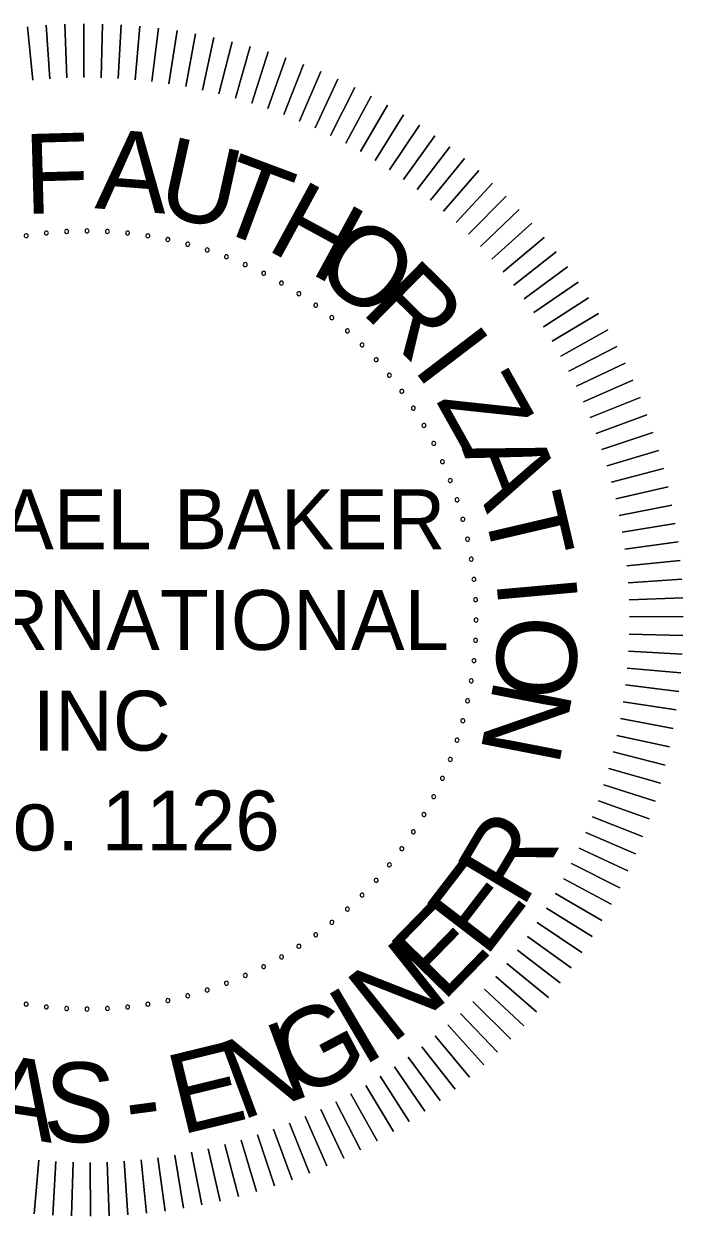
# Model space of a CAD drawing. Extents: x -4306 to 3843, y 131 to 8053.
# Drawn here: x 2834.9 to 2972.5, y 322.6 to 571.4 of the extents above; entities that cross this region are included whole.
import ezdxf

# ---------------------------------------------------------------- set-up
doc = ezdxf.new("R2010")
doc.units = 0
doc.layers.add('G-ANNO-TEXT', color=7, linetype='Continuous')

msp = doc.modelspace()

# ---------------------------------------------------------------- linework, layer by layer
at = {"layer": 'G-ANNO-TEXT'}
for points in [[(2836.77, 559.65), (2835.65, 570.82)], [(2835.65, 570.82), (2836.77, 559.65)], [(2840.32, 559.95), (2839.55, 571.14)], [(2839.55, 571.14), (2840.32, 559.95)], [(2843.87, 560.13), (2843.45, 571.35)], [(2843.45, 571.35), (2843.87, 560.13)], [(2847.42, 560.21), (2847.36, 571.43)], [(2847.36, 571.43), (2847.42, 560.21)], [(2850.98, 560.17), (2851.27, 571.39)], [(2851.27, 571.39), (2850.98, 560.17)], [(2854.53, 560.03), (2855.18, 571.23)], [(2855.18, 571.23), (2854.53, 560.03)], [(2858.08, 559.77), (2859.08, 570.95)], [(2859.08, 570.95), (2858.08, 559.77)], [(2861.62, 559.4), (2862.96, 570.54)], [(2862.96, 570.54), (2861.62, 559.4)], [(2865.14, 558.92), (2866.84, 570.01)], [(2866.84, 570.01), (2865.14, 558.92)], [(2868.65, 558.32), (2870.69, 569.36)], [(2870.69, 569.36), (2868.65, 558.32)], [(2872.14, 557.62), (2874.52, 568.59)], [(2874.52, 568.59), (2872.14, 557.62)], [(2875.6, 556.81), (2878.33, 567.7)], [(2878.33, 567.7), (2875.6, 556.81)], [(2879.04, 555.89), (2882.11, 566.69)], [(2882.11, 566.69), (2879.04, 555.89)], [(2882.44, 554.86), (2885.85, 565.56)], [(2885.85, 565.56), (2882.44, 554.86)], [(2885.81, 553.73), (2889.56, 564.31)], [(2889.56, 564.31), (2885.81, 553.73)], [(2889.15, 552.49), (2893.22, 562.95)], [(2893.22, 562.95), (2889.15, 552.49)], [(2892.44, 551.15), (2896.84, 561.47)], [(2896.84, 561.47), (2892.44, 551.15)], [(2895.69, 549.7), (2900.41, 559.88)], [(2900.41, 559.88), (2895.69, 549.7)], [(2898.89, 548.16), (2903.93, 558.18)], [(2903.93, 558.18), (2898.89, 548.16)], [(2902.05, 546.51), (2907.4, 556.37)], [(2907.4, 556.37), (2902.05, 546.51)], [(2905.14, 544.77), (2910.8, 554.46)], [(2910.8, 554.46), (2905.14, 544.77)], [(2908.19, 542.92), (2914.15, 552.43)], [(2914.15, 552.43), (2908.19, 542.92)], [(2911.17, 540.99), (2917.43, 550.3)], [(2917.43, 550.3), (2911.17, 540.99)], [(2914.09, 538.96), (2920.64, 548.07)], [(2920.64, 548.07), (2914.09, 538.96)], [(2916.95, 536.84), (2923.78, 545.74)], [(2923.78, 545.74), (2916.95, 536.84)], [(2919.74, 534.63), (2926.84, 543.32)], [(2926.84, 543.32), (2919.74, 534.63)], [(2922.45, 532.34), (2929.83, 540.8)], [(2929.83, 540.8), (2922.45, 532.34)], [(2932.73, 538.18), (2925.1, 529.96)], [(2925.1, 529.96), (2932.73, 538.18)], [(2935.56, 535.48), (2927.67, 527.5)], [(2927.67, 527.5), (2935.56, 535.48)], [(2938.29, 532.68), (2930.16, 524.96)], [(2930.16, 524.96), (2938.29, 532.68)], [(2940.94, 529.81), (2932.56, 522.34)], [(2932.56, 522.34), (2940.94, 529.81)], [(2943.5, 526.85), (2934.89, 519.65)], [(2934.89, 519.65), (2943.5, 526.85)], [(2945.96, 523.81), (2937.13, 516.88)], [(2937.13, 516.88), (2945.96, 523.81)], [(2948.32, 520.7), (2939.28, 514.05)], [(2939.28, 514.05), (2948.32, 520.7)], [(2950.59, 517.51), (2941.34, 511.15)], [(2941.34, 511.15), (2950.59, 517.51)], [(2952.75, 514.26), (2943.31, 508.19)], [(2943.31, 508.19), (2952.75, 514.26)], [(2954.81, 510.94), (2945.18, 505.17)], [(2945.18, 505.17), (2954.81, 510.94)], [(2956.77, 507.55), (2946.96, 502.09)], [(2946.96, 502.09), (2956.77, 507.55)], [(2958.62, 504.11), (2948.65, 498.96)], [(2948.65, 498.96), (2958.62, 504.11)], [(2960.36, 500.6), (2950.23, 495.77)], [(2950.23, 495.77), (2960.36, 500.6)], [(2961.98, 497.05), (2951.71, 492.54)], [(2951.71, 492.54), (2961.98, 497.05)], [(2963.5, 493.45), (2953.09, 489.26)], [(2953.09, 489.26), (2963.5, 493.45)], [(2964.9, 489.8), (2954.37, 485.94)], [(2954.37, 485.94), (2964.9, 489.8)], [(2966.19, 486.11), (2955.54, 482.58)], [(2955.54, 482.58), (2966.19, 486.11)], [(2967.36, 482.38), (2956.6, 479.19)], [(2956.6, 479.19), (2967.36, 482.38)], [(2968.41, 478.61), (2957.56, 475.76)], [(2957.56, 475.76), (2968.41, 478.61)], [(2969.35, 474.82), (2958.41, 472.31)], [(2958.41, 472.31), (2969.35, 474.82)], [(2970.16, 470.99), (2959.15, 468.83)], [(2959.15, 468.83), (2970.16, 470.99)], [(2970.85, 467.15), (2959.78, 465.33)], [(2959.78, 465.33), (2970.85, 467.15)], [(2971.43, 463.28), (2960.3, 461.81)], [(2960.3, 461.81), (2971.43, 463.28)], [(2971.88, 459.39), (2960.71, 458.28)], [(2960.71, 458.28), (2971.88, 459.39)], [(2972.21, 455.5), (2961.01, 454.73)], [(2961.01, 454.73), (2972.21, 455.5)], [(2972.41, 451.6), (2961.2, 451.18)], [(2961.2, 451.18), (2972.41, 451.6)], [(2972.49, 447.69), (2961.27, 447.62)], [(2961.27, 447.62), (2972.49, 447.69)], [(2972.46, 443.78), (2961.24, 444.07)], [(2961.24, 444.07), (2972.46, 443.78)], [(2972.29, 439.87), (2961.09, 440.51)], [(2961.09, 440.51), (2972.29, 439.87)], [(2972.01, 435.97), (2960.83, 436.97)], [(2960.83, 436.97), (2972.01, 435.97)], [(2971.6, 432.09), (2960.46, 433.43)], [(2960.46, 433.43), (2971.6, 432.09)], [(2971.07, 428.21), (2959.98, 429.91)], [(2959.98, 429.91), (2971.07, 428.21)], [(2970.42, 424.36), (2959.39, 426.4)], [(2959.39, 426.4), (2970.42, 424.36)], [(2969.65, 420.52), (2958.68, 422.91)], [(2958.68, 422.91), (2969.65, 420.52)], [(2968.76, 416.72), (2957.87, 419.45)], [(2957.87, 419.45), (2968.76, 416.72)], [(2967.75, 412.94), (2956.95, 416.01)], [(2956.95, 416.01), (2967.75, 412.94)], [(2966.62, 409.2), (2955.93, 412.61)], [(2955.93, 412.61), (2966.62, 409.2)], [(2965.37, 405.49), (2954.79, 409.24)], [(2954.79, 409.24), (2965.37, 405.49)], [(2964.01, 401.83), (2953.55, 405.9)], [(2953.55, 405.9), (2964.01, 401.83)], [(2962.54, 398.21), (2952.21, 402.61)], [(2952.21, 402.61), (2962.54, 398.21)], [(2960.95, 394.64), (2950.77, 399.36)], [(2950.77, 399.36), (2960.95, 394.64)], [(2959.25, 391.12), (2949.22, 396.16)], [(2949.22, 396.16), (2959.25, 391.12)], [(2957.44, 387.65), (2947.57, 393)], [(2947.57, 393), (2957.44, 387.65)], [(2955.52, 384.25), (2945.83, 389.9)], [(2945.83, 389.9), (2955.52, 384.25)], [(2953.49, 380.9), (2943.99, 386.86)], [(2943.99, 386.86), (2953.49, 380.9)], [(2951.37, 377.62), (2942.05, 383.88)], [(2942.05, 383.88), (2951.37, 377.62)], [(2949.14, 374.41), (2940.02, 380.96)], [(2940.02, 380.96), (2949.14, 374.41)], [(2946.81, 371.27), (2937.9, 378.1)], [(2937.9, 378.1), (2946.81, 371.27)], [(2944.38, 368.21), (2935.69, 375.31)], [(2935.69, 375.31), (2944.38, 368.21)], [(2941.86, 365.22), (2933.4, 372.6)], [(2933.4, 372.6), (2941.86, 365.22)], [(2939.24, 362.31), (2931.02, 369.95)], [(2931.02, 369.95), (2939.24, 362.31)], [(2936.54, 359.49), (2928.56, 367.38)], [(2928.56, 367.38), (2936.54, 359.49)], [(2933.75, 356.76), (2926.02, 364.89)], [(2926.02, 364.89), (2933.75, 356.76)], [(2930.87, 354.11), (2923.4, 362.49)], [(2923.4, 362.49), (2930.87, 354.11)], [(2927.91, 351.55), (2920.71, 360.16)], [(2920.71, 360.16), (2927.91, 351.55)], [(2924.87, 349.09), (2917.95, 357.92)], [(2917.95, 357.92), (2924.87, 349.09)], [(2918.57, 344.46), (2912.21, 353.71)], [(2912.21, 353.71), (2918.57, 344.46)], [(2921.76, 346.73), (2915.11, 355.77)], [(2915.11, 355.77), (2921.76, 346.73)], [(2915.32, 342.3), (2909.25, 351.74)], [(2909.25, 351.74), (2915.32, 342.3)], [(2912, 340.24), (2906.23, 349.86)], [(2906.23, 349.86), (2912, 340.24)], [(2905.17, 336.43), (2900.02, 346.4)], [(2900.02, 346.4), (2905.17, 336.43)], [(2908.61, 338.28), (2903.15, 348.08)], [(2903.15, 348.08), (2908.61, 338.28)], [(2901.67, 334.69), (2896.83, 344.82)], [(2896.83, 344.82), (2901.67, 334.69)], [(2894.51, 331.55), (2890.32, 341.96)], [(2890.32, 341.96), (2894.51, 331.55)], [(2898.11, 333.06), (2893.6, 343.34)], [(2893.6, 343.34), (2898.11, 333.06)], [(2887.17, 328.86), (2883.64, 339.51)], [(2883.64, 339.51), (2887.17, 328.86)], [(2890.86, 330.15), (2887, 340.68)], [(2887, 340.68), (2890.86, 330.15)], [(2875.88, 325.7), (2873.37, 336.64)], [(2873.37, 336.64), (2875.88, 325.7)], [(2879.67, 326.64), (2876.82, 337.49)], [(2876.82, 337.49), (2879.67, 326.64)], [(2883.44, 327.69), (2880.25, 338.45)], [(2880.25, 338.45), (2883.44, 327.69)], [(2837.04, 323.04), (2838.03, 334.22)], [(2838.03, 334.22), (2837.04, 323.04)], [(2840.93, 322.76), (2841.58, 333.96)], [(2841.58, 333.96), (2840.93, 322.76)], [(2844.84, 322.59), (2845.13, 333.81)], [(2845.13, 333.81), (2844.84, 322.59)], [(2848.75, 322.55), (2848.69, 333.78)], [(2848.69, 333.78), (2848.75, 322.55)], [(2852.66, 322.64), (2852.24, 333.85)], [(2852.24, 333.85), (2852.66, 322.64)], [(2856.56, 322.84), (2855.79, 334.04)], [(2855.79, 334.04), (2856.56, 322.84)], [(2860.46, 323.17), (2859.34, 334.34)], [(2859.34, 334.34), (2860.46, 323.17)], [(2864.34, 323.62), (2862.87, 334.75)], [(2862.87, 334.75), (2864.34, 323.62)], [(2868.21, 324.19), (2866.39, 335.27)], [(2866.39, 335.27), (2868.21, 324.19)], [(2872.05, 324.89), (2869.89, 335.9)], [(2869.89, 335.9), (2872.05, 324.89)]]:
    msp.add_lwpolyline(points, dxfattribs=at)
for centre, start, end in [((2835.35, 527.21), 9, 189), ((2839.57, 527.76), 6, 186), ((2839.57, 527.76), 186, 6), ((2843.8, 528.1), 3, 183), ((2843.8, 528.1), 183, 3), ((2848.06, 528.21), 0, 180), ((2848.06, 528.21), 180, 0), ((2852.31, 528.1), 357, 177), ((2852.31, 528.1), 177, 357), ((2856.54, 527.76), 354, 174), ((2856.54, 527.76), 174, 354), ((2860.76, 527.21), 351, 171), ((2835.35, 527.21), 189, 9), ((2860.76, 527.21), 171, 351), ((2864.94, 526.43), 168, 348), ((2864.94, 526.43), 348, 168), ((2869.08, 525.44), 165, 345), ((2869.08, 525.44), 345, 165), ((2873.15, 524.23), 162, 342), ((2873.15, 524.23), 342, 162), ((2877.16, 522.81), 159, 339), ((2877.16, 522.81), 339, 159), ((2881.09, 521.19), 156, 336), ((2881.09, 521.19), 336, 156), ((2884.93, 519.36), 153, 333), ((2884.93, 519.36), 333, 153), ((2888.66, 517.33), 330, 150), ((2888.66, 517.33), 150, 330), ((2892.29, 515.11), 147, 327), ((2892.29, 515.11), 327, 147), ((2895.79, 512.7), 144, 324), ((2895.79, 512.7), 324, 144), ((2899.17, 510.11), 141, 321), ((2899.17, 510.11), 321, 141), ((2902.4, 507.35), 318, 138), ((2902.4, 507.35), 138, 318), ((2905.48, 504.42), 135, 315), ((2905.48, 504.42), 315, 135), ((2908.41, 501.34), 132, 312), ((2908.41, 501.34), 312, 132), ((2911.17, 498.1), 129, 309), ((2911.17, 498.1), 309, 129), ((2913.76, 494.73), 126, 306), ((2913.76, 494.73), 306, 126), ((2916.17, 491.23), 123, 303), ((2916.17, 491.23), 303, 123), ((2918.39, 487.6), 120, 300), ((2918.39, 487.6), 300, 120), ((2920.42, 483.86), 117, 297), ((2920.42, 483.86), 297, 117), ((2922.25, 480.03), 114, 294), ((2922.25, 480.03), 294, 114), ((2923.88, 476.1), 111, 291), ((2923.88, 476.1), 291, 111), ((2925.3, 472.09), 108, 288), ((2925.3, 472.09), 288, 108), ((2926.5, 468.01), 105, 285), ((2926.5, 468.01), 285, 105), ((2927.5, 463.88), 102, 282), ((2927.5, 463.88), 282, 102), ((2928.27, 459.7), 99, 279), ((2928.27, 459.7), 279, 99), ((2928.83, 455.48), 96, 276), ((2928.83, 455.48), 276, 96), ((2929.16, 451.24), 93, 273), ((2929.16, 451.24), 273, 93), ((2929.27, 446.99), 90, 270), ((2929.27, 446.99), 270, 90), ((2929.16, 442.74), 87, 267), ((2929.16, 442.74), 267, 87), ((2928.83, 438.5), 84, 264), ((2928.83, 438.5), 264, 84), ((2928.27, 434.29), 81, 261), ((2928.27, 434.29), 261, 81), ((2927.5, 430.11), 78, 258), ((2927.5, 430.11), 258, 78), ((2926.5, 425.97), 75, 255), ((2926.5, 425.97), 255, 75), ((2925.3, 421.9), 72, 252), ((2925.3, 421.9), 252, 72), ((2923.88, 417.89), 69, 249), ((2923.88, 417.89), 249, 69), ((2922.25, 413.96), 66, 246), ((2922.25, 413.96), 246, 66), ((2920.42, 410.12), 63, 243), ((2920.42, 410.12), 243, 63), ((2918.39, 406.39), 60, 240), ((2918.39, 406.39), 240, 60), ((2916.17, 402.76), 57, 237), ((2916.17, 402.76), 237, 57), ((2913.76, 399.26), 54, 234), ((2913.76, 399.26), 234, 54), ((2911.17, 395.88), 51, 231), ((2911.17, 395.88), 231, 51), ((2908.41, 392.65), 48, 228), ((2908.41, 392.65), 228, 48), ((2905.48, 389.57), 45, 225), ((2905.48, 389.57), 225, 45), ((2902.4, 386.64), 42, 222), ((2902.4, 386.64), 222, 42), ((2899.17, 383.88), 39, 219), ((2899.17, 383.88), 219, 39), ((2895.79, 381.29), 36, 216), ((2895.79, 381.29), 216, 36), ((2892.29, 378.88), 33, 213), ((2892.29, 378.88), 213, 33), ((2888.66, 376.66), 30, 210), ((2888.66, 376.66), 210, 30), ((2884.93, 374.63), 27, 207), ((2884.93, 374.63), 207, 27), ((2877.16, 371.17), 21, 201), ((2877.16, 371.17), 201, 21), ((2881.09, 372.8), 24, 204), ((2881.09, 372.8), 204, 24), ((2869.08, 368.55), 15, 195), ((2869.08, 368.55), 195, 15), ((2873.15, 369.75), 18, 198), ((2873.15, 369.75), 198, 18), ((2835.35, 366.78), 171, 351), ((2835.35, 366.78), 351, 171), ((2839.57, 366.22), 354, 174), ((2839.57, 366.22), 174, 354), ((2843.8, 365.89), 357, 177), ((2843.8, 365.89), 177, 357), ((2848.06, 365.78), 0, 180), ((2852.31, 365.89), 3, 183), ((2852.31, 365.89), 183, 3), ((2856.54, 366.22), 6, 186), ((2856.54, 366.22), 186, 6), ((2860.76, 366.78), 9, 189), ((2860.76, 366.78), 189, 9), ((2864.94, 367.55), 12, 192), ((2864.94, 367.55), 192, 12), ((2848.06, 365.78), 180, 0)]:
    msp.add_arc(centre, 0.417, start, end, dxfattribs=at)

# ---------------------------------------------------------------- texts
for s, rotation, p in [('F', 1.5867, (2835.12, 531.73)), ('A', 355.5955, (2849.57, 532.95)), ('U', 347.5481, (2862.18, 531.76)), ('T', 339.5007, (2873.82, 528.98)), ('H', 331.4533, (2885.12, 524.52)), ('O', 323.4059, (2894.69, 519.25)), ('R', 315.3585, (2905.02, 511.35)), ('I', 307.3112, (2915.86, 499.61)), ('Z', 299.2638, (2920.75, 492.82)), ('A', 291.2164, (2926.22, 482.8)), ('T', 283.169, (2930.57, 471)), ('I', 275.1216, (2933.46, 455.4)), ('O', 267.0743, (2934.05, 448.24)), ('N', 259.0269, (2933.17, 435.14)), ('R', 59.2262, (2938.92, 386.55)), ('E', 52.4765, (2931.19, 376.29)), ('E', 45.7268, (2922.3, 367.01)), ('N', 38.4196, (2911.53, 358.22)), ('I', 30.5495, (2905.47, 353.63)), ('G', 27.7404, (2892.3, 346.63)), ('N', 20.4332, (2880.16, 342.43)), ('E', 13.6835, (2867.6, 339.49)), ('A', 351.1991, (2826, 340.11)), ('S', 357.9489, (2838.72, 338.26)), ('-', 7.5077, (2856.91, 338.22))]:
    msp.add_text(s, height=16.67, rotation=rotation, dxfattribs=at).set_placement(p)
for s, height, p in [('MICHAEL BAKER', 12.5016, (2787.23, 461.77)), (' INTERNATIONAL', 12.5016, (2785.22, 440.75)), ('INC', 12.502, (2836.73, 419.73)), (' No. 1126', 12.502, (2815.79, 398.89))]:
    msp.add_text(s, height=height, dxfattribs=at).set_placement(p)

doc.saveas('drawing.dxf')
